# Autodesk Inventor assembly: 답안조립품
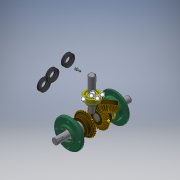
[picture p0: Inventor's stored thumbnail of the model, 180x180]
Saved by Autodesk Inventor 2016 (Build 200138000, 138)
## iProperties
Created: 2019-08
Part Number: 답안조립품
Material: 일반
Document SubType Name: Assembly
Designer: user
Author: user
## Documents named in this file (15)
- D:\490823V1006\답안조립품.iam
- D:\490823V1006\메인 베벨기어.ipt
- D:\490823V1006\메인 축.ipt
- 메인 축.ipt
- D:\490823V1006\베어링 6203.ipt
- D:\490823V1006\본체.ipt
- D:\490823V1006\볼트 M4.ipt
- 볼트 M4.ipt
- D:\490823V1006\서브 베벨기어.ipt
- D:\490823V1006\서브 축.ipt
- 서브 축.ipt
- D:\490823V1006\오일 실.ipt
- 오일 실.ipt
- D:\490823V1006\커버.ipt
- D:\490823V1006\키 5x5.ipt
